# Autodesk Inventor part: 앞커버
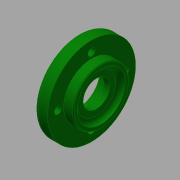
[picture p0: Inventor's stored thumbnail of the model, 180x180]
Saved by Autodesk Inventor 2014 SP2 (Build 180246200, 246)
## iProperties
Created: 2015-12
Part Number: 앞커버
Material: 알루미늄 6061
Document SubType Name: Modeling
Designer: mduedu
Density: 2.71 g/cm^3
Appearance: 진녹색
Author: mduedu
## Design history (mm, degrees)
sketch "스케치1"
  geometry: L1 (0, 0)-(14, 0); L2 (14, 0)-(14, 17.5); L3 (14, 17.5)-(8, 17.5); L4 (8, 17.5)-(8, 27.5); L5 (8, 27.5)-(0, 27.5); L6 (0, 27.5)-(0, 0)
  constraints: 12 end point, 4 parallel, 1 horizontal, 1 perpendicular
  dimensions: "d0" = 14 distance between parallel lines of L2 L6; "d2" = 8 distance of L4.end L5.end; "d3" = 55 diameter of L5 L1; "d4" = 35 diameter of L3 L1
revolve "회전1" sketch "스케치1" stored, may be unused: angle "d5" = 90 deg
hole "구멍1" diameter "d8" = 30; stored, may be unused: countersink angle "d12" = 90 deg, drill point angle "d14" = 0 deg; dims "d6" = 10, "d7" = 10, "d9" = 6, "d10" = 4, "d11" = 2, "d13" = 3
hole "구멍2" diameter "d17" = 25; stored, may be unused: countersink angle "d21" = 90 deg, drill point angle "d23" = 0 deg; dims "d15" = 10, "d16" = 10, "d18" = 6, "d19" = 4, "d20" = 2, "d22" = 7.3
hole "구멍3" diameter "d26" = 16.5; stored, may be unused: countersink angle "d30" = 90 deg, drill point angle "d32" = 0 deg; dims "d24" = 10, "d25" = 10, "d27" = 6, "d28" = 4, "d29" = 2, "d31" = 7.3
fillet "모깎기1" dims "d33" = 0.3
chamfer "모따기1" distance "d34" = 1; stored, may be unused: second distance "d35" = 2, angle "d36" = 30 deg
fillet "모깎기2" dims "d37" = 3
fillet "모깎기3" dims "d38" = 2
chamfer "모따기2" distance "d39" = 0.5; stored, may be unused: second distance "d40" = 2, angle "d41" = 45 deg
sketch "스케치2" dims "d42" = 42
  geometry: 9 further points
  constraints: 3 coincident, 2 vertical alignment, 9 other
  dimensions: "d46" = 360 deg dimension on point (0, 0) point (0, 21) (derived)
sketch "스케치3"
  geometry: 4 further points
hole "구멍4" sketch "스케치3" at (-21, 0), (0, -21), (21, 0), (0, 21) diameter "d50" = 4.5; stored, may be unused: countersink angle "d54" = 90 deg, drill point angle "d56" = 0 deg; dims "d51" = 6, "d52" = 8, "d53" = 4.6, "d55" = 8
node "솔리드1"
